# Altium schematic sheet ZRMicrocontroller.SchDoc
size A4; PageSetup: Record=PageOptions¦CenterHorizontal=True¦CenterVertical=True¦PrintScale=0.91¦XCorrection=1.00¦YCorrection=1.00¦PrintKind=0¦BorderSize=5000000¦LeftOffset=0¦BottomOffset=0¦Orientation=2¦PaperLength=1000¦PaperWidth=1000¦Scale=100¦PaperSource=7¦PrintQuality=-3¦MediaType=1¦DitherType=10¦PrintScaleMode=1¦PaperKind=A4¦PaperIndex=9
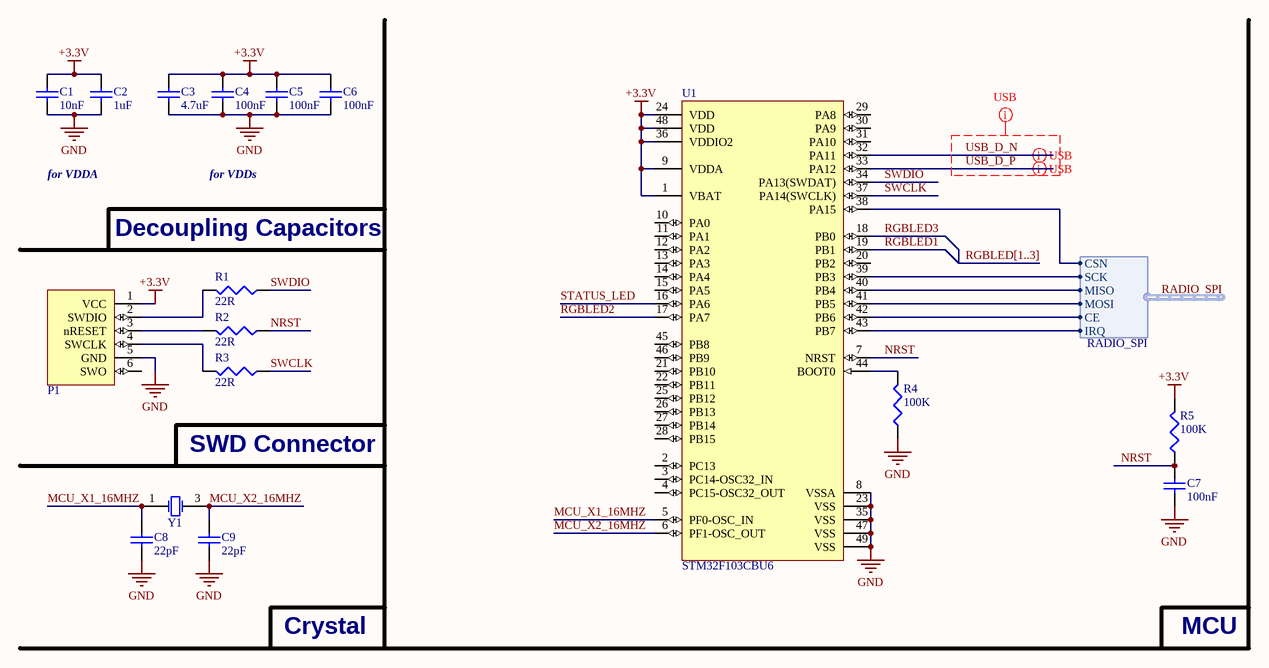
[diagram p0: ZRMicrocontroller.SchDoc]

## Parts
C1  10nF  [0402]
C2  1uF  [0603]
C3  4.7uF  [0603]
C4  100nF  [0402]
C5  100nF  [0402]
C6  100nF  [0402]
C7  100nF  [0402]
C8  22pF  [0402]
C9  22pF  [0402]
P1  TC2030-IDC-NL  [TC2030-IDC-NL]  (value not drawn)
R1  22R  [0402]
R2  22R  [0402]
R3  22R  [0402]
R4  100K  [0402]
R5  100K  [0402]
U1  STM32F103CBU6  [QFN50P700X700X60_HS-49L]
Y1  7V-16.000MAAE-T  [3.2x2.5 CRYSTAL]  (value not drawn)

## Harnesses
RADIO_SPI: MOSI, MISO, SCK, CSN, CE, IRQ

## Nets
+3.3V: C1.2 C2.2 C3.2 C4.2 C5.2 C6.2 P1.1(VCC) R5.2 U1.1(VBAT) U1.9(VDDA) U1.24(VDD) U1.36(VDDIO2) U1.48(VDD)
GND: C1.1 C2.1 C3.1 C4.1 C5.1 C6.1 C7.1 C8.1 C9.1 P1.5(GND) R4.1 U1.8(VSSA) U1.23(VSS) U1.35(VSS) U1.47(VSS) U1.49(VSS) Y1.2(GND) Y1.4(GND)
MCU_X1_16MHZ: C8.2 U1.5(PF0-OSC_IN) Y1.1(X1)
MCU_X2_16MHZ: C9.2 U1.6(PF1-OSC_OUT) Y1.3(X2)
NRST: C7.2 R2.1 R5.1 U1.7(NRST)
RADIO_SPI.CE: U1.42(PB6) ; harness RADIO_SPI.CE
RADIO_SPI.CSN: U1.38(PA15) ; harness RADIO_SPI.CSN
RADIO_SPI.IRQ: U1.43(PB7) ; harness RADIO_SPI.IRQ
RADIO_SPI.MISO: U1.40(PB4) ; harness RADIO_SPI.MISO
RADIO_SPI.MOSI: U1.41(PB5) ; harness RADIO_SPI.MOSI
RADIO_SPI.SCK: U1.39(PB3) ; harness RADIO_SPI.SCK
RGBLED1: U1.19(PB1)
RGBLED2: U1.17(PA7)
RGBLED3: U1.18(PB0)
STATUS_LED: U1.16(PA6)
SWCLK: R3.1 U1.37(PA14(SWCLK))
SWDIO: R1.1 U1.34(PA13(SWDAT))
USB_D_N: U1.32(PA11)
USB_D_P: U1.33(PA12)
NetP1_2: P1.2(SWDIO) R1.2
NetP1_3: P1.3(nRESET) R2.2
NetP1_4: P1.4(SWCLK) R3.2
NetR4_2: R4.2 U1.44(BOOT0)

Not connected (* = marked no-connect by the designer): P1 6(SWO); U1 2(PC13) 3(PC14-OSC32_IN) 4(PC15-OSC32_OUT) 10(PA0) 11(PA1) 12(PA2) 13(PA3) 14(PA4) 15(PA5) 20(PB2) 21(PB10) 22(PB11) 25(PB12) 26(PB13) 27(PB14) 28(PB15) 29(PA8) 30(PA9) 31(PA10) 45(PB8) 46(PB9)

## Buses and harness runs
bus RGBLED[1..3]

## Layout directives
differential pair: USB_D_N, USB_D_P
net class USB: USB_D_N, USB_D_P

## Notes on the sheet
- for VDDA
- Decoupling Capacitors
- for VDDs
- SWD Connector
- Crystal
- MCU

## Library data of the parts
C1 = 10nF: 10nF 0402 X7R 25V ±5%
C2 = 1uF: 1uF 0603 X5R 10V ±10%
C3 = 4.7uF: 4.7uF 0603 X5R 10V ±10%
C4-C7 = 100nF: 100nF 0402 X7R 16V ±10%
C8 C9 = 22pF: 22pF 0402 NP0/CG0 50V ±5%
P1 = TC2030-IDC-NL: TagConnect TC2030-IDC-NL SWD Programming Connector
R1-R3 = 22R: 22R 0402 1/16W ±1%
R4 R5 = 100K: 100K 0402 1/16W ±1%
U1 = STM32F103CBU6: STMICROELECTRONICS  STM32F103CBU6 ARM Cortex-M3, 72 MHz, 128 KB, 20 KB, 48, VFQFPN
Y1 = 7V-16.000MAAE-T: TXC - 7V-16.000MAAE-T, 16MHZ, 30PPM, 12PF - CRYSTAL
